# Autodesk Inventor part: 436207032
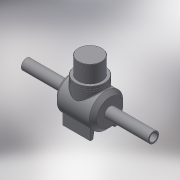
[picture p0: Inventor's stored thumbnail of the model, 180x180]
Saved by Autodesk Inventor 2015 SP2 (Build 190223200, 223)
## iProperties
Created: 2017-08
Part Number: 436207032
Material: Generic
Description: PLASSON PE BALL VALVE 32
Document SubType Name: Modeling
Designer: Кирилл
Density: 1 g/cm^3
Appearance: Default
Author: Кирилл
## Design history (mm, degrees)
derived "436207.ipt"
feature "Solid1::436207.ipt"
feature "Solid2::436207.ipt"
tag "TaggingFeature1"
body "Solid1"
other parameters: "d1" = 32, "d3" = 103, "d5" = 24, "d6" = 9, "d8" = 94, "d11" = 56, "d12" = 0.7, "d13" = 4, "d14" = 4, "d16" = 100 deg, "d17" = 32, "d18" = 6.4, "d20" = 65, "d21" = 0, "d22" = 0.7, "d26" = 3, "d28" = 0, "d29" = 1.4, "d_" = 32, "s_" = 3, "L_1" = 103, "B_" = 65, "H_" = 94
